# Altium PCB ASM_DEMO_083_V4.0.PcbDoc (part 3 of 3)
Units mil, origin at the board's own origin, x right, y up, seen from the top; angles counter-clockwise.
Board outline 4534.65 x 3225.59 mil, 2 copper layers (Top Layer, Bottom Layer); 192 components, 109 nets, 496 pads, 1295 vias.
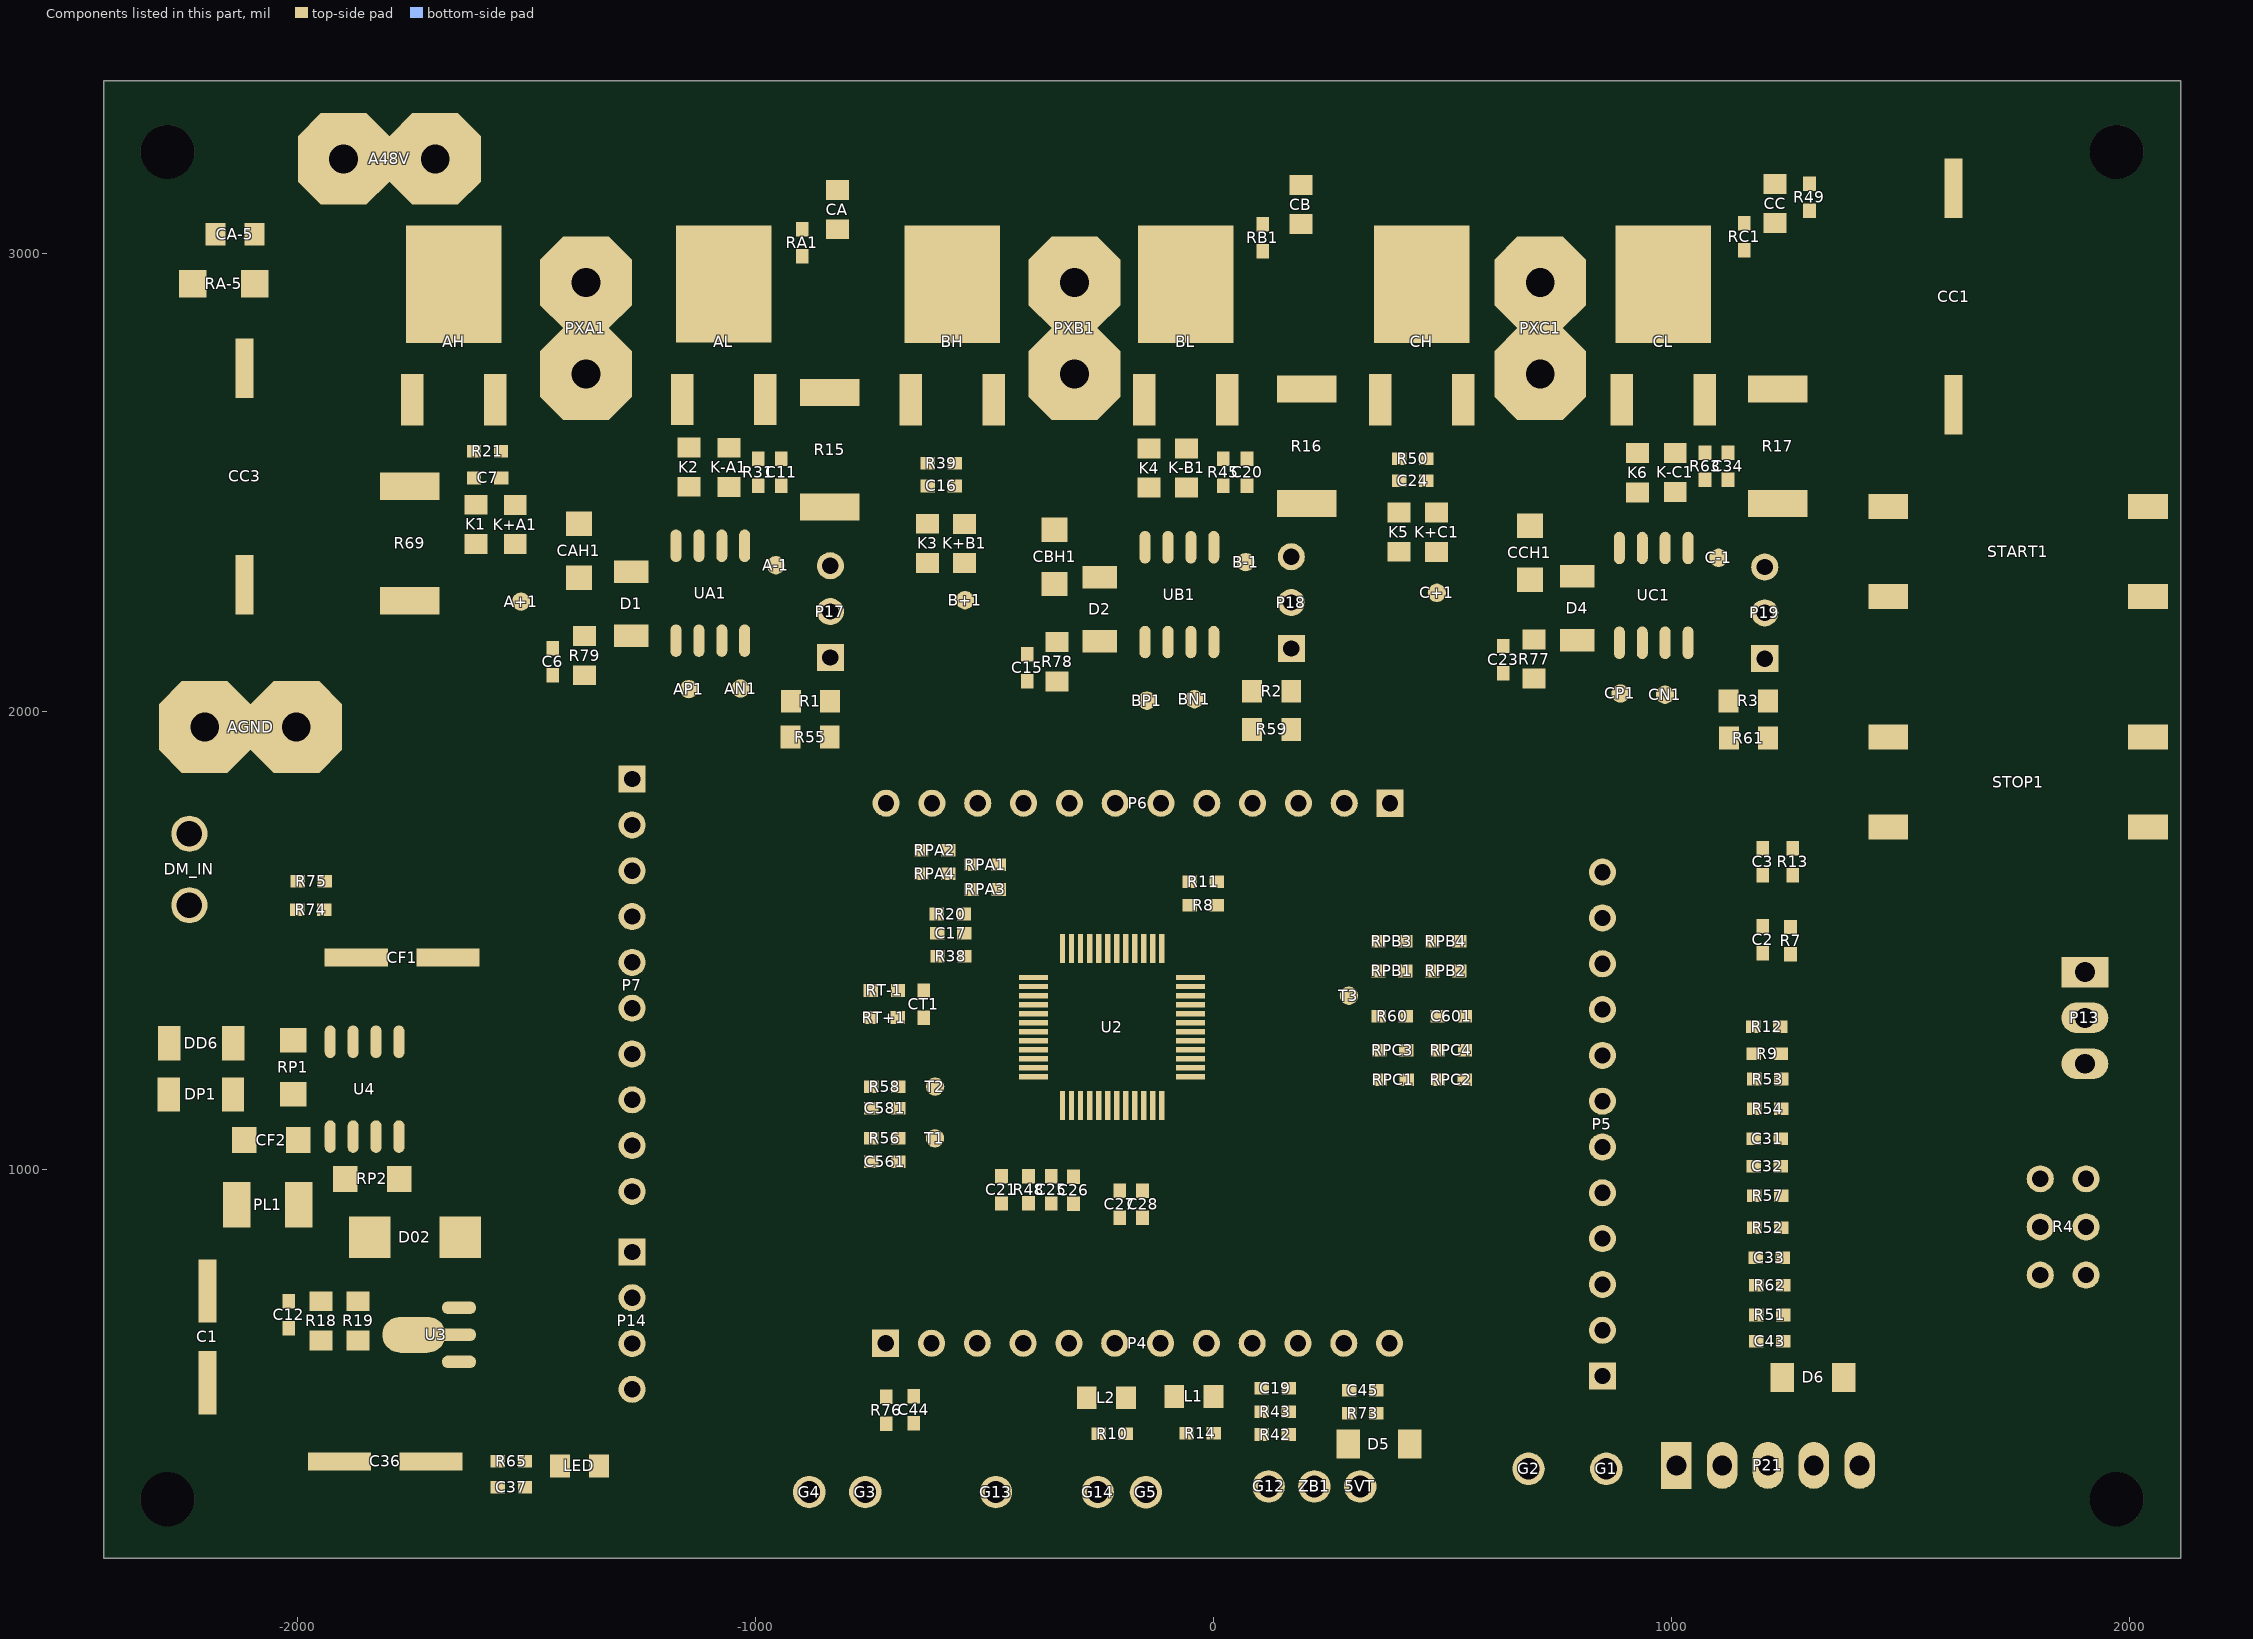
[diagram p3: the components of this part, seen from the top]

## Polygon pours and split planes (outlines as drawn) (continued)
AX on Bottom Solder "Bottom Layer-No Net" (solid): -1416.93,3054.72 -1454.33,3017.32 -1454.33,2992.13 -1454.33,2782.28 -1486.61,2750 -1489.37,2747.24 -1592.91,2747.24 -1593.7,2747.24 -1612.2,2728.74 -1614.96,2725.98 -1614.96,2645.67 -1614.96,2635.43 -1603.94,2624.41 -1603.15,2623.62 -1283.07,2623.62 -1229.13,2623.62 -1217.32,2635.43 -1216.93,2635.83 -1216.93,2752.76 -1216.93,2763.78 -1197.64,2783.07 -1188.98,2791.73 -1025.59,2791.73 -972.44,2791.73 -959.45,2804.72 -959.45,3043.7 -959.45,3045.28 -968.5,3054.33

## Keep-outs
Keep-Out Layer:
  lines w5: -2341.73,3377.56 1619.29,3377.56 2025.2,3377.56 ; -2336.22,3377.56 ccw(c-2336.22,3290.94) -2422.83,3290.94 -2422.83,244.09 ccw(c-2331.1,244.09) -2331.1,152.36 ; -2331.1,151.97 1192.47,151.97 2025.59,151.97 ; 2025.2,3377.17 cw(c2025.2,3290.55) 2111.81,3290.55 2111.81,238.98 ; 2025.59,152.36 ccw(c2025.59,238.98) 2112.2,238.98

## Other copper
Top Layer:
  pour cut-out: -2459.06,3137.8 -2459.06,3101.57 -2449.21,3091.73 -2149.21,3091.73 -2149.21,3134.65 -2152.36,3137.8
  pour cut-out: -1775.59,2329.53 -1775.59,2275.98 -1686.22,2275.98 -1684.65,2277.56 -1682.68,2275.59 -1682.68,1962.2 -1580.71,1860.63 -1436.61,1860.24 -1416.14,1882.28 -1224.02,1882.28 -779.92,1446.06 -779.92,1396.06 -779.53,1374.8 -730.31,1374.8 -730.71,1409.45 -740.16,1448.03 -1201.18,1907.48 -1431.1,1907.87 -1459.84,1878.74 -1522.05,1876.38 -1650.79,1981.43 -1650.79,2307.87 -1672.83,2329.92
  pour cut-out: -2449.21,470.08 -2117.72,470.08 -2062.2,414.57 -2062.2,115.75 -2447.64,115.75 -2449.21,117.32
  pour cut-out: 2158.66,493.31 2157.09,494.88 1702.36,494.88 1639.76,432.28 1639.76,157.87 2128.74,157.87 2164.57,193.7
  pour cut-out: 1781.5,3405.51 1775.2,3399.21 1775.2,3007.87 1776.77,3006.3 1864.96,3006.3 1864.96,3392.91 1846.06,3411.81
Bottom Layer:
  pour cut-out: -2459.06,3137.8 -2459.06,3101.57 -2449.21,3091.73 -2149.21,3091.73 -2149.21,3134.65 -2152.36,3137.8
  pour cut-out: -2450,469.29 -2118.5,469.29 -2062.99,413.78 -2062.99,114.96 -2448.43,114.96 -2450,116.54
  pour cut-out: 2158.86,493.9 2157.28,495.47 1702.56,495.47 1639.96,432.87 1639.96,158.46 2128.94,158.46 2164.76,194.29
  pour cut-out: 1781.5,3404.72 1775.2,3398.43 1775.2,3007.09 1776.77,3005.51 1864.96,3005.51 1864.96,3392.13 1846.06,3411.02

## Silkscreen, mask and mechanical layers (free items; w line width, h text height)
Top Overlay:
  text "ASM_DEMO_083_V4.0" at -371.89,3237.8 h70
  text "+48V" at -1528.74,3195.28 h100
  text "C" at 682.68,3094.88 h100
  text "B" at -324.8,3087.8 h100
  text "A" at -1375.2,3082.68 h100
  text "START" at 1326.38,2540.94 h60
  text "P19" at 1301.97,2282.68 h60 r90
  text "P17" at -737.4,2276.38 h60 r90
  text "P18" at 277.95,2274.02 h60 r90
  text "PGND" at -2191.34,2109.45 h100
  text "STOP" at 1365.75,2048.03 h60
  text "AN" at -268.11,1871.26 h60
  text "AP" at -368.11,1870.08 h60
  text "BN" at -51.57,1869.68 h60
  text "BP" at -149.21,1868.9 h60
  text "CP" at 54.33,1868.5 h60
  text "CN" at 148.43,1868.5 h60
  text "P7" at -1386.61,1865.35 h60
  text "P6" at -832.28,1809.45 h60
  text "DM_IN" at -2003.15,1770.87 h100
  text "P5" at 821.65,1714.57 h60
  text "GND" at 1637.8,1431.5 h70
  text "TXD" at 1637.8,1321.26 h70
  text "RXD" at 1637.8,1218.9 h70
  text "R4" at 1601.18,921.26 h60
  text "P14" at -1420.87,882.28 h60
  text "5V" at -1188.19,848.82 h60
  text "CLK" at -1194.88,757.87 h60
  text "DIO" at -1200,638.58 h60
  text "P4" at -836.22,616.14 h60
  text "GND" at -1202.36,536.61 h60
  text "P21" at 1532.28,480.71 h60
  text "GND" at 927.56,198.43 h70
  text "C" at 1102.76,197.64 h70
  text "GND" at 62.6,195.67 h60
  text "5V" at 292.13,196.46 h60
  text "B" at 1205.91,196.06 h70
  text "5VH" at 1390.55,196.06 h70
  text "A" at 1306.3,194.88 h70
  text "ZB" at 192.91,194.49 h60
  text "GND" at -940.94,188.58 h60
Bottom Overlay:
  text "ASM_DEMO_083_V4.0" at -371.89,3237.8 h70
